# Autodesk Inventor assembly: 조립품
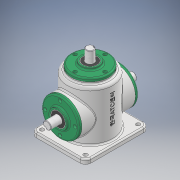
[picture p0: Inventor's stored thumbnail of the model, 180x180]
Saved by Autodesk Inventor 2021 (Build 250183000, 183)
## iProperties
Created: 2021-02
Part Number: 조립품
Document SubType Name: Assembly
Designer: 201-09
Author: 201-09
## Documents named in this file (14)
- C:\Users\201-09\Desktop\710215V1002\조립품.iam
- C:\Users\201-09\Desktop\710215V1002\본체.ipt
- C:\Users\201-09\Desktop\710215V1002\커버.ipt
- C:\Users\201-09\Desktop\710215V1002\베어링 6203.ipt
- C:\Users\201-09\Desktop\710215V1002\오일 실.ipt
- 오일 실.ipt
- C:\Users\201-09\Desktop\710215V1002\메인 축.ipt
- 메인 축.ipt
- C:\Users\201-09\Desktop\710215V1002\키 5x5.ipt
- C:\Users\201-09\Desktop\710215V1002\메인 베벨기어.ipt
- C:\Users\201-09\Desktop\710215V1002\서브 축.ipt
- 서브 축.ipt
- C:\Users\201-09\Desktop\710215V1002\키 4x4.ipt
- C:\Users\201-09\Desktop\710215V1002\서브 베벨기어.ipt
